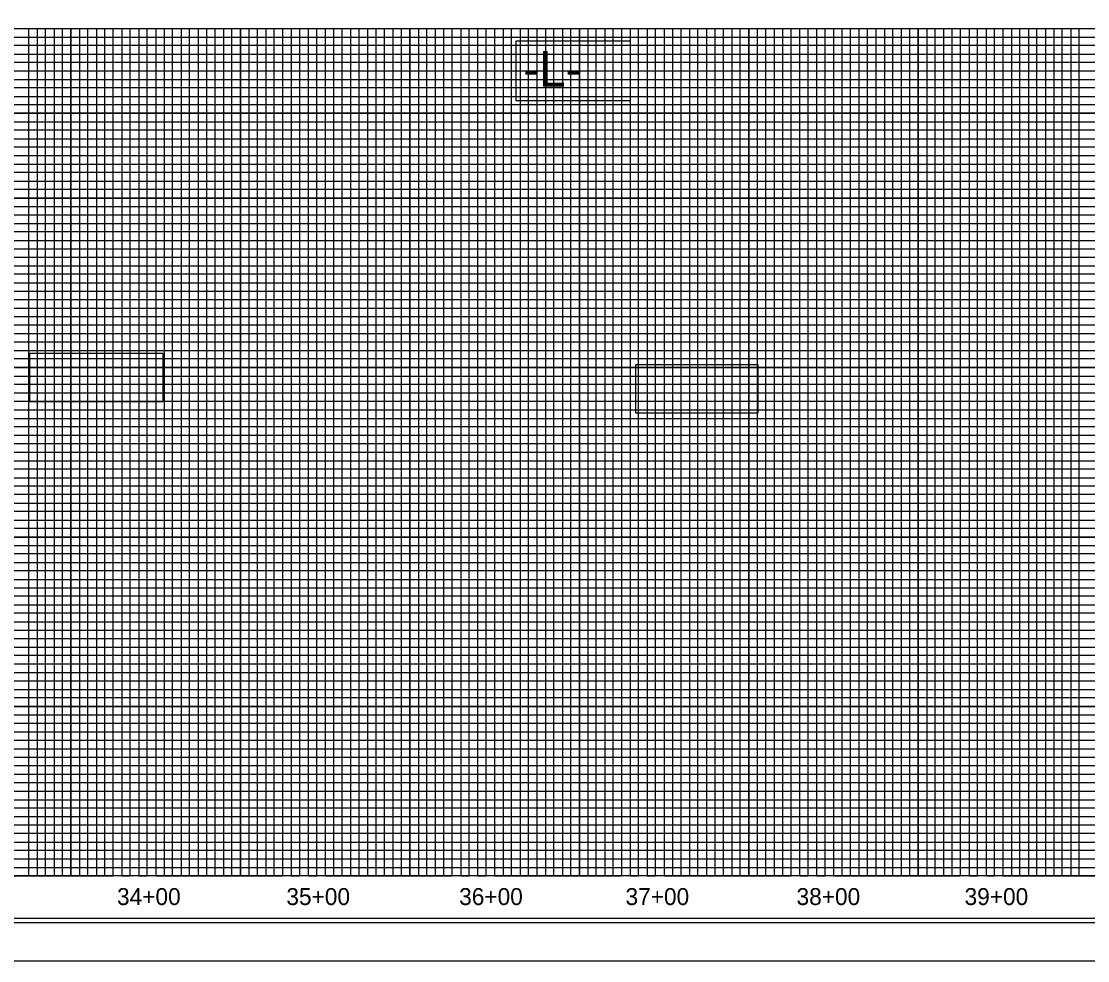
# Model space of a CAD drawing. Extents: x 1810963 to 1812948, y 722070 to 723250.
# Drawn here: x 1811601 to 1812230, y 722070 to 722624 of the extents above; entities that cross this region are included whole.
import ezdxf

# ---------------------------------------------------------------- set-up
doc = ezdxf.new("R2010")
doc.units = 0
for name, color, linetype in [('Exist Vertical Profile Horizontal Axis Label Major', 7, 'Continuous'), ('Prop Grid Mask', 7, 'Continuous'), ('Prop Horizontal Alignment Station Label', 7, 'Continuous'), ('Sheet Cutting Line CELL', 7, 'Continuous'), ('Sheet DOT Grid CELL', 7, 'Continuous'), ('Sheet Layout Profile Border Port 2', 7, 'Continuous'), ('Sheet Plot Border Inside CELL', 7, 'Continuous'), ('Sheet Plot Border Outside CELL', 7, 'Continuous'), ('Sheet Profile CELL', 7, 'Continuous'), ('Sheet Profile Grid Major CELL', 7, 'Continuous'), ('Sheet Profile Grid Middle CELL', 7, 'Continuous'), ('Sheet Profile Grid Minor CELL', 7, 'Continuous')]:
    doc.layers.add(name, color=color, linetype=linetype)

msp = doc.modelspace()

# ---------------------------------------------------------------- linework, layer by layer
at = {"layer": 'Prop Grid Mask'}
for points in [[(1811893.13, 722612.66), (1811960.48, 722612.66), (1811960.48, 722577.28), (1811893.13, 722577.28)], [(1811606.2, 722428.28), (1811684.75, 722428.28), (1811684.75, 722399.63), (1811606.2, 722399.63)], [(1811963.71, 722421.6), (1812035.87, 722421.6), (1812035.87, 722392.87), (1811963.71, 722392.87)]]:
    msp.add_lwpolyline(points, close=True, dxfattribs=at)
at = {"layer": 'Sheet Cutting Line CELL'}
msp.add_line((1810963.46, 722069.88), (1812647.46, 722069.88), dxfattribs=at)
at = {"layer": 'Sheet DOT Grid CELL'}
for p, q in [((1811130.46, 722619.88), (1812630.35, 722619.88)), ((1811630.46, 722619.88), (1811630.46, 722119.88)), ((1811680.46, 722619.88), (1811680.46, 722119.88)), ((1811730.46, 722619.88), (1811730.46, 722119.88)), ((1811780.46, 722619.88), (1811780.46, 722119.88)), ((1811830.46, 722619.88), (1811830.46, 722119.88)), ((1811880.46, 722619.88), (1811880.46, 722119.88)), ((1811930.46, 722619.88), (1811930.46, 722119.88)), ((1811980.46, 722619.88), (1811980.46, 722119.88)), ((1812030.46, 722619.88), (1812030.46, 722119.88)), ((1812080.46, 722619.88), (1812080.46, 722119.88)), ((1812130.46, 722619.88), (1812130.46, 722119.88)), ((1812180.46, 722619.88), (1812180.46, 722119.88)), ((1811130.46, 722569.88), (1812630.35, 722569.88)), ((1811130.46, 722519.88), (1812630.35, 722519.88)), ((1811130.46, 722469.88), (1812630.35, 722469.88)), ((1811130.46, 722419.88), (1812630.35, 722419.88)), ((1811130.46, 722369.88), (1812630.35, 722369.88)), ((1811130.46, 722319.88), (1812630.35, 722319.88)), ((1811130.46, 722269.88), (1812630.35, 722269.88)), ((1811130.46, 722219.88), (1812630.35, 722219.88)), ((1811130.46, 722169.88), (1812630.35, 722169.88))]:
    msp.add_line(p, q, dxfattribs=at)
at = {"layer": 'Sheet Layout Profile Border Port 2'}
msp.add_lwpolyline([(1811180.46, 722619.88), (1812580.46, 722619.88), (1812580.46, 722119.88), (1811180.46, 722119.88)], close=True, dxfattribs=at)
at = {"layer": 'Sheet Plot Border Inside CELL'}
msp.add_lwpolyline([(1810976.46, 722092.33), (1812642.96, 722092.33), (1812642.96, 723147.43), (1810976.46, 723147.43)], close=True, dxfattribs=at)
at = {"layer": 'Sheet Plot Border Outside CELL'}
msp.add_lwpolyline([(1810963.46, 722069.88), (1812647.46, 722069.88), (1812647.46, 723169.88), (1810963.46, 723169.88)], close=True, dxfattribs=at)
at = {"layer": 'Sheet Profile CELL'}
for p, q in [((1811130.46, 722619.88), (1812630.46, 722619.88)), ((1812630.46, 722119.88), (1811130.46, 722119.88)), ((1811130.46, 722094.88), (1812630.46, 722094.88))]:
    msp.add_line(p, q, dxfattribs=at)
msp.add_lwpolyline([(1812630.46, 723144.88), (1811130.46, 723144.88), (1811130.46, 722094.88), (1812630.46, 722094.88)], close=True, dxfattribs=at)
at = {"layer": 'Sheet Profile Grid Major CELL'}
for p, q in [((1811630.46, 722619.88), (1811680.46, 722619.88)), ((1811730.46, 722619.88), (1811780.46, 722619.88)), ((1811830.46, 722619.88), (1811880.46, 722619.88)), ((1811930.46, 722619.88), (1811980.46, 722619.88)), ((1812030.46, 722619.88), (1812080.46, 722619.88)), ((1812130.46, 722619.88), (1812180.46, 722619.88))]:
    msp.add_line(p, q, dxfattribs=at)
for points in [[(1811580.46, 722119.88), (1811630.46, 722119.88), (1811630.46, 722619.88), (1811680.46, 722619.88), (1811680.46, 722119.88), (1811730.46, 722119.88), (1811730.46, 722619.88), (1811780.46, 722619.88), (1811780.46, 722119.88), (1811830.46, 722119.88), (1811830.46, 722619.88), (1811880.46, 722619.88), (1811880.46, 722119.88), (1811930.46, 722119.88), (1811930.46, 722619.88), (1811980.46, 722619.88), (1811980.46, 722119.88), (1812030.46, 722119.88), (1812030.46, 722619.88), (1812080.46, 722619.88), (1812080.46, 722119.88), (1812130.46, 722119.88), (1812130.46, 722619.88), (1812180.46, 722619.88), (1812180.46, 722119.88), (1812230.46, 722119.88)], [(1812630.46, 722569.88), (1811130.46, 722569.88)], [(1812630.46, 722519.88), (1811130.46, 722519.88), (1811130.46, 722469.88), (1812630.46, 722469.88)], [(1812630.46, 722419.88), (1811130.46, 722419.88), (1811130.46, 722369.88), (1812630.46, 722369.88)], [(1812630.46, 722319.88), (1811130.46, 722319.88), (1811130.46, 722269.88), (1812630.46, 722269.88)], [(1812630.46, 722219.88), (1811130.46, 722219.88), (1811130.46, 722219.88), (1811130.46, 722169.88), (1812630.46, 722169.88)], [(1812630.46, 722119.88), (1811130.46, 722119.88)]]:
    msp.add_lwpolyline(points, dxfattribs=at)
at = {"layer": 'Sheet Profile Grid Middle CELL'}
for points in [[(1811555.46, 722619.88), (1811605.46, 722619.88), (1811605.46, 722119.88), (1811655.46, 722119.88), (1811655.46, 722619.88), (1811705.46, 722619.88), (1811705.46, 722119.88), (1811755.46, 722119.88), (1811755.46, 722119.88), (1811755.46, 722619.88), (1811805.46, 722619.88), (1811805.46, 722119.88), (1811855.46, 722119.88), (1811855.46, 722619.88), (1811905.46, 722619.88), (1811905.46, 722119.88), (1811955.46, 722119.88), (1811955.46, 722619.88), (1812005.46, 722619.88), (1812005.46, 722119.88), (1812055.46, 722119.88), (1812055.46, 722619.88), (1812105.46, 722619.88), (1812105.46, 722119.88), (1812155.46, 722119.88), (1812155.46, 722619.88), (1812205.46, 722619.88), (1812205.46, 722119.88), (1812255.46, 722119.88)], [(1811130.46, 722594.88), (1812630.46, 722594.88)], [(1812630.46, 722544.88), (1811130.46, 722544.88), (1811130.46, 722494.88), (1812630.46, 722494.88)], [(1812630.46, 722444.88), (1811130.46, 722444.88), (1811130.46, 722394.88), (1812630.46, 722394.88)], [(1812630.46, 722344.88), (1811130.46, 722344.88), (1811130.46, 722294.88), (1812630.46, 722294.88)], [(1812630.46, 722244.88), (1811130.46, 722244.88), (1811130.46, 722194.88), (1812630.46, 722194.88)], [(1812630.46, 722144.88), (1811130.46, 722144.88)]]:
    msp.add_lwpolyline(points, dxfattribs=at)
at = {"layer": 'Sheet Profile Grid Minor CELL'}
for p, q in [((1811180.46, 722614.88), (1812580.46, 722614.88)), ((1812580.46, 722609.88), (1811180.46, 722609.88)), ((1811180.46, 722604.88), (1812580.46, 722604.88)), ((1812580.46, 722599.88), (1811180.46, 722599.88)), ((1811180.46, 722589.88), (1812580.46, 722589.88)), ((1812580.46, 722584.88), (1811180.46, 722584.88)), ((1811180.46, 722579.88), (1812580.46, 722579.88)), ((1812580.46, 722574.88), (1811180.46, 722574.88)), ((1811180.46, 722564.88), (1812580.46, 722564.88)), ((1812580.46, 722559.88), (1811180.46, 722559.88)), ((1811180.46, 722554.88), (1812580.46, 722554.88)), ((1812580.46, 722549.88), (1811180.46, 722549.88)), ((1811180.46, 722539.88), (1812580.46, 722539.88)), ((1812580.46, 722534.88), (1811180.46, 722534.88)), ((1811180.46, 722529.88), (1812580.46, 722529.88)), ((1812580.46, 722524.88), (1811180.46, 722524.88)), ((1811180.46, 722514.88), (1812580.46, 722514.88)), ((1812580.46, 722509.88), (1811180.46, 722509.88)), ((1811180.46, 722504.88), (1812580.46, 722504.88)), ((1812580.46, 722499.88), (1811180.46, 722499.88)), ((1811180.46, 722489.88), (1812580.46, 722489.88)), ((1812580.46, 722484.88), (1811180.46, 722484.88)), ((1811180.46, 722479.88), (1812580.46, 722479.88)), ((1812580.46, 722474.88), (1811180.46, 722474.88)), ((1811180.46, 722464.88), (1812580.46, 722464.88)), ((1812580.46, 722459.88), (1811180.46, 722459.88)), ((1811180.46, 722454.88), (1812580.46, 722454.88)), ((1812580.46, 722449.88), (1811180.46, 722449.88)), ((1811180.46, 722439.88), (1812580.46, 722439.88)), ((1812580.46, 722434.88), (1811180.46, 722434.88)), ((1811180.46, 722429.88), (1812580.46, 722429.88)), ((1812580.46, 722424.88), (1811180.46, 722425.03)), ((1811180.46, 722414.88), (1812580.46, 722414.88)), ((1812580.46, 722409.88), (1811180.46, 722409.88)), ((1811180.46, 722404.88), (1812580.46, 722404.88)), ((1812580.46, 722399.88), (1811180.46, 722399.88)), ((1811180.46, 722389.88), (1812580.46, 722389.88)), ((1812580.46, 722384.88), (1811180.46, 722384.88)), ((1811180.46, 722379.88), (1812580.46, 722379.88)), ((1812580.46, 722374.88), (1811180.46, 722374.88)), ((1811180.46, 722364.88), (1812580.46, 722364.88)), ((1812580.46, 722359.88), (1811180.46, 722359.88)), ((1811180.46, 722354.88), (1812580.46, 722354.88)), ((1812580.46, 722349.88), (1811180.46, 722349.88)), ((1811180.46, 722339.88), (1812580.46, 722339.88)), ((1812580.46, 722334.88), (1811180.46, 722334.88)), ((1811180.46, 722329.88), (1812580.46, 722329.88)), ((1812580.46, 722324.88), (1811180.46, 722324.88)), ((1811180.46, 722314.88), (1812580.46, 722314.88)), ((1812580.46, 722309.88), (1811180.46, 722309.88)), ((1811180.46, 722304.88), (1812580.46, 722304.88)), ((1812580.46, 722299.88), (1811180.46, 722299.88)), ((1811180.46, 722289.88), (1812580.46, 722289.88)), ((1812580.46, 722284.88), (1811180.46, 722284.88)), ((1811180.46, 722279.88), (1812580.46, 722279.88)), ((1812580.46, 722274.88), (1811180.46, 722274.88)), ((1811180.46, 722264.88), (1812580.46, 722264.88)), ((1812580.46, 722259.88), (1811180.46, 722259.88)), ((1811180.46, 722254.88), (1812580.46, 722254.88)), ((1812580.46, 722249.88), (1811180.46, 722249.88)), ((1811180.46, 722239.88), (1812580.46, 722239.88)), ((1812580.46, 722234.88), (1811180.46, 722234.88)), ((1811180.46, 722229.88), (1812580.46, 722229.88)), ((1812580.46, 722224.88), (1811180.46, 722224.88)), ((1811180.46, 722214.88), (1812580.46, 722214.88)), ((1812580.46, 722209.88), (1811180.46, 722209.88)), ((1811180.46, 722204.88), (1812580.46, 722204.88)), ((1812580.46, 722199.88), (1811180.46, 722199.88)), ((1811180.46, 722189.88), (1812580.46, 722189.88)), ((1812580.46, 722184.88), (1811180.46, 722184.88)), ((1811180.46, 722179.88), (1812580.46, 722179.88)), ((1812580.46, 722174.88), (1811180.46, 722174.88)), ((1811180.46, 722164.88), (1812580.46, 722164.88)), ((1812580.46, 722159.88), (1811180.46, 722159.88)), ((1811180.46, 722154.88), (1812580.46, 722154.88)), ((1812580.46, 722149.88), (1811180.46, 722149.88)), ((1811180.46, 722139.88), (1812580.46, 722139.88)), ((1812580.46, 722134.88), (1811180.46, 722134.88)), ((1811180.46, 722129.88), (1812580.46, 722129.88)), ((1811180.46, 722124.88), (1812580.46, 722124.88))]:
    msp.add_line(p, q, dxfattribs=at)
for points in [[(1811600.46, 722619.88), (1811610.46, 722619.88), (1811610.46, 722119.88), (1811615.46, 722119.88), (1811615.46, 722619.88), (1811620.46, 722619.88), (1811620.46, 722119.88), (1811625.46, 722119.88), (1811625.46, 722619.88), (1811635.46, 722619.88), (1811635.46, 722119.88), (1811640.46, 722119.88), (1811640.46, 722619.88), (1811645.46, 722619.88), (1811645.46, 722119.88), (1811650.46, 722119.88), (1811650.46, 722619.88), (1811660.46, 722619.88), (1811660.46, 722119.88), (1811665.46, 722119.88), (1811665.46, 722619.88), (1811670.46, 722619.88), (1811670.46, 722119.88), (1811675.46, 722119.88), (1811675.46, 722619.88), (1811685.46, 722619.88), (1811685.46, 722119.88), (1811690.46, 722119.88), (1811690.46, 722619.88), (1811695.46, 722619.88), (1811695.46, 722119.88), (1811700.46, 722119.88), (1811700.46, 722619.88), (1811710.46, 722619.88)], [(1811710.46, 722619.88), (1811710.46, 722119.88), (1811715.46, 722119.88), (1811715.46, 722619.88), (1811720.46, 722619.88), (1811720.46, 722119.88), (1811725.46, 722119.88), (1811725.46, 722619.88), (1811735.46, 722619.88), (1811735.46, 722119.88), (1811740.46, 722119.88), (1811740.46, 722619.88), (1811745.46, 722619.88), (1811745.46, 722119.88), (1811750.46, 722119.88), (1811750.46, 722619.88), (1811760.46, 722619.88), (1811760.46, 722119.88), (1811765.46, 722119.88), (1811765.46, 722619.88), (1811770.46, 722619.88), (1811770.46, 722119.88), (1811775.46, 722119.88), (1811775.46, 722619.88), (1811785.46, 722619.88), (1811785.46, 722119.88), (1811790.46, 722119.88), (1811790.46, 722619.88), (1811795.46, 722619.88), (1811795.46, 722119.88), (1811800.46, 722119.88), (1811800.46, 722619.88), (1811810.46, 722619.88), (1811810.46, 722119.88), (1811815.46, 722119.88), (1811815.46, 722619.88), (1811820.46, 722619.88), (1811820.46, 722119.88), (1811825.46, 722119.88), (1811825.46, 722619.88), (1811835.46, 722619.88), (1811835.46, 722119.88), (1811835.46, 722119.88), (1811840.46, 722119.88), (1811840.46, 722619.88), (1811845.46, 722619.88), (1811845.46, 722119.88), (1811850.46, 722119.88), (1811850.46, 722619.88), (1811860.46, 722619.88), (1811860.46, 722119.88), (1811865.46, 722119.88), (1811865.46, 722619.88), (1811870.46, 722619.88), (1811870.46, 722119.88), (1811875.46, 722119.88), (1811875.46, 722619.88), (1811885.46, 722619.88), (1811885.46, 722119.88), (1811890.46, 722119.88), (1811890.46, 722619.88), (1811895.46, 722619.88), (1811895.46, 722119.88), (1811900.46, 722119.88), (1811900.46, 722619.88), (1811910.46, 722619.88), (1811910.46, 722119.88), (1811915.46, 722119.88), (1811915.46, 722619.88), (1811920.46, 722619.88), (1811920.46, 722119.88), (1811925.46, 722119.88), (1811925.46, 722619.88), (1811935.46, 722619.88), (1811935.46, 722119.88), (1811940.46, 722119.88), (1811940.46, 722619.88), (1811945.46, 722619.88), (1811945.46, 722119.88), (1811950.46, 722119.88), (1811950.46, 722619.88), (1811960.46, 722619.88), (1811960.46, 722119.88), (1811965.46, 722119.88), (1811965.46, 722619.88), (1811970.46, 722619.88), (1811970.46, 722119.88), (1811975.46, 722119.88), (1811975.46, 722619.88), (1811985.46, 722619.88), (1811985.46, 722119.88), (1811990.16, 722120.43), (1811990.46, 722119.88), (1811990.46, 722619.88), (1811995.46, 722619.88), (1811995.46, 722119.88), (1812000.46, 722119.88), (1812000.46, 722619.88), (1812010.46, 722619.88), (1812010.46, 722119.88), (1812015.46, 722119.88)], [(1812015.46, 722119.88), (1812015.46, 722619.88), (1812020.46, 722619.88), (1812020.46, 722119.88), (1812025.46, 722119.88), (1812025.46, 722619.88), (1812035.46, 722619.88), (1812035.46, 722119.88), (1812040.46, 722119.88), (1812040.46, 722619.88), (1812045.46, 722619.88), (1812045.46, 722119.88), (1812050.46, 722119.88), (1812050.46, 722619.88), (1812060.46, 722619.88), (1812060.46, 722119.88), (1812065.46, 722119.88), (1812065.46, 722619.88), (1812070.46, 722619.88), (1812070.46, 722119.88), (1812075.46, 722119.88), (1812075.46, 722619.88), (1812085.46, 722619.88), (1812085.46, 722119.88), (1812090.46, 722119.88), (1812090.46, 722619.88), (1812095.46, 722619.88), (1812095.46, 722119.88), (1812100.46, 722119.88), (1812100.46, 722619.88), (1812110.46, 722619.88), (1812110.46, 722119.88), (1812115.46, 722119.88), (1812115.46, 722619.88), (1812120.46, 722619.88), (1812120.46, 722119.88), (1812125.46, 722119.88), (1812125.46, 722619.88), (1812135.46, 722619.88), (1812135.46, 722119.88), (1812140.46, 722119.88), (1812140.46, 722619.88), (1812145.46, 722619.88), (1812145.46, 722119.88), (1812150.46, 722119.88), (1812150.46, 722619.88), (1812160.46, 722619.88), (1812160.46, 722119.88), (1812165.46, 722119.88), (1812165.46, 722619.88), (1812170.46, 722619.88), (1812170.46, 722119.88), (1812175.46, 722119.88), (1812175.46, 722619.88), (1812185.46, 722619.88), (1812185.46, 722119.88), (1812190.46, 722119.88), (1812190.46, 722619.88), (1812195.46, 722619.88), (1812195.46, 722119.88), (1812200.46, 722119.88), (1812200.46, 722619.88), (1812210.46, 722619.88), (1812210.46, 722119.88), (1812215.46, 722119.88), (1812215.46, 722619.88), (1812220.46, 722619.88), (1812220.46, 722119.88), (1812225.46, 722119.88), (1812225.46, 722619.88), (1812235.46, 722619.88)]]:
    msp.add_lwpolyline(points, dxfattribs=at)

# ---------------------------------------------------------------- texts
at = {"layer": 'Exist Vertical Profile Horizontal Axis Label Major'}
for s, p in [('34+00', (1811657.64, 722102.7)), ('35+00', (1811757.58, 722102.7)), ('36+00', (1811859.54, 722102.7)), ('37+00', (1811957.72, 722102.7)), ('38+00', (1812058.64, 722102.7)), ('39+00', (1812157.81, 722102.7))]:
    msp.add_text(s, height=10, dxfattribs=at).set_placement(p)
at = {"layer": 'Prop Horizontal Alignment Station Label'}
msp.add_text('-L-', height=21, rotation=360, dxfattribs=at).set_placement((1811897.42, 722585.71))

doc.saveas('drawing.dxf')
